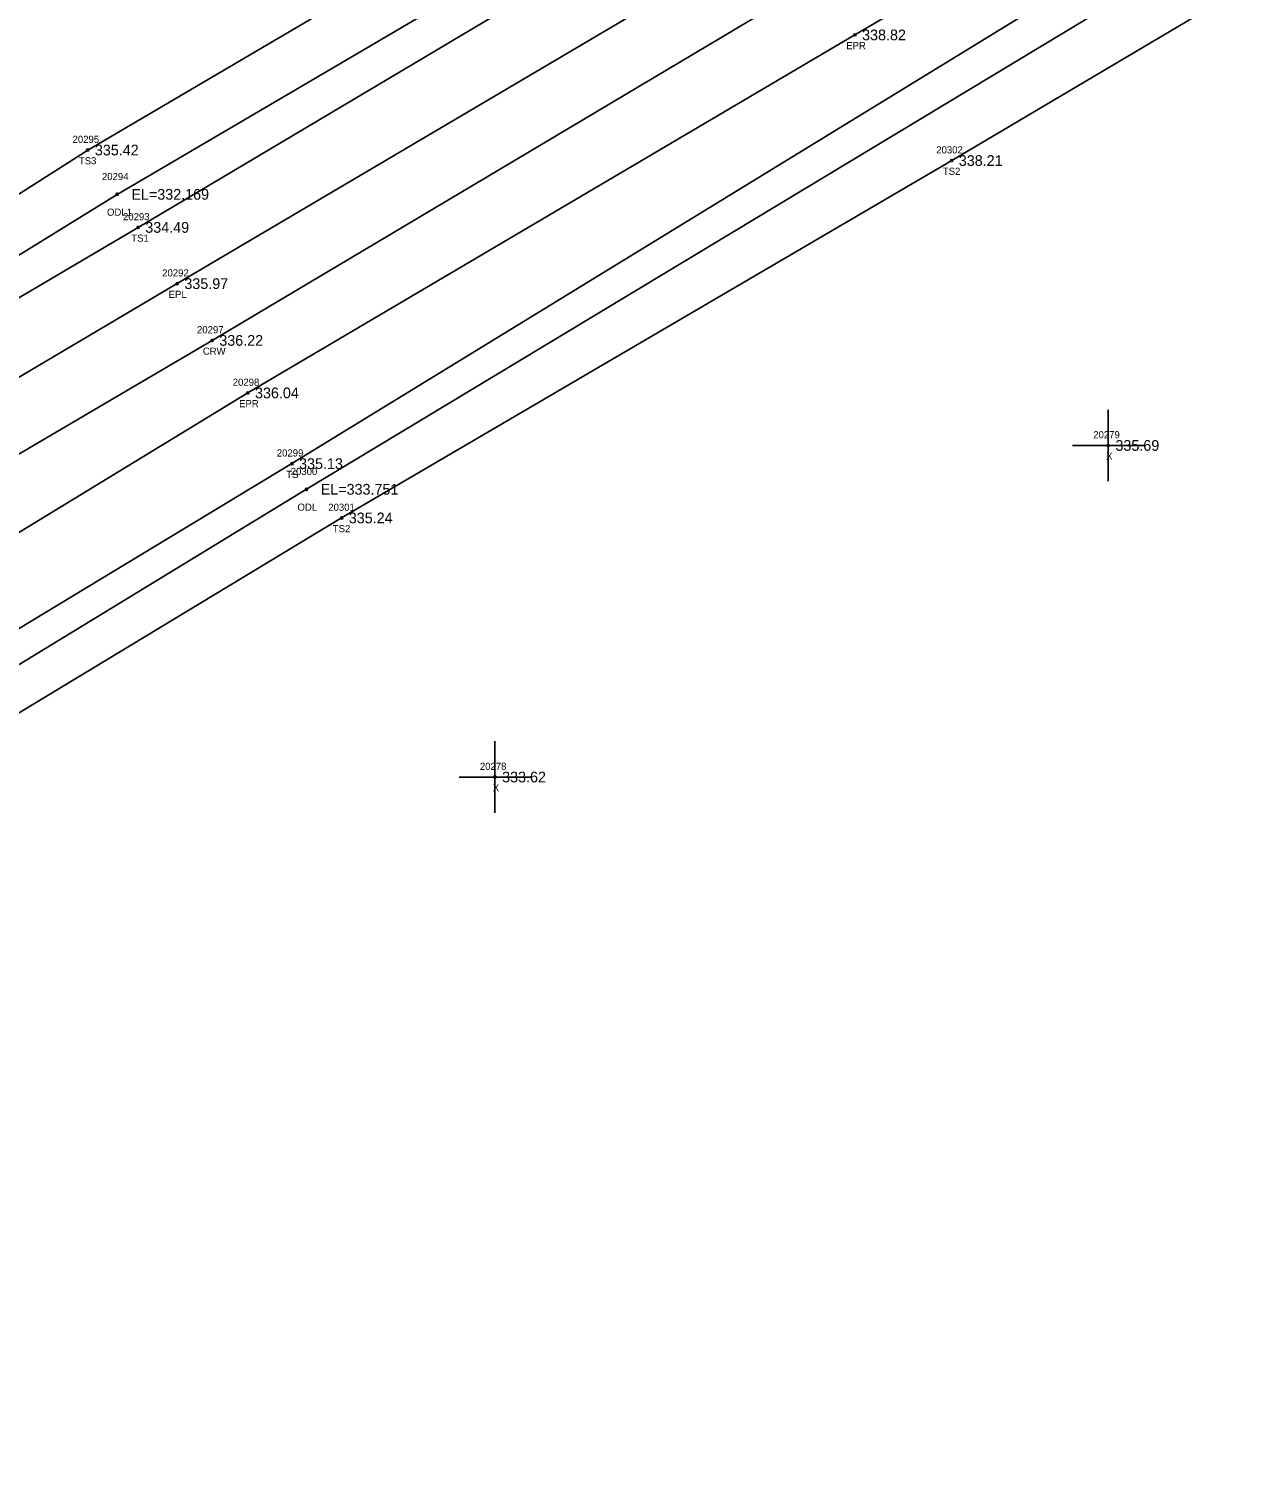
# Model space of a CAD drawing. Extents: x 2231109 to 2232328, y 1035718 to 1036919.
# Drawn here: x 2231830.7 to 2232002.6, y 1036455.4 to 1036655.6 of the extents above; entities that cross this region are included whole.
import ezdxf

# ---------------------------------------------------------------- set-up
doc = ezdxf.new("R2010")
doc.units = 0
for name, color, linetype in [('RD_DTM_BkLn1', 7, 'Continuous'), ('RD_DTM_BkLn2', 7, 'Continuous'), ('RD_DTM_BkLn_txCode', 7, 'Continuous'), ('RD_EX_H2O', 7, 'Continuous'), ('RD_EX_H2O_txCode', 7, 'Continuous'), ('RD_EX_Misc', 7, 'Continuous'), ('RD_EX_Misc_txCode', 7, 'Continuous'), ('RD_EX_Road', 7, 'Continuous'), ('RD_EX_Road_txCode', 7, 'Continuous'), ('RD_EX_TX_H2O_ELEV', 7, 'Continuous'), ('RD_EX_TX_Misc_ELEV', 7, 'Continuous'), ('RD_EX_TX_Road_ELEV', 7, 'Continuous'), ('RD_HC_Survey_ELEV', 7, 'Continuous'), ('RD_HC_Survey_txCode', 7, 'Continuous'), ('RD_SMD_Locator', 7, 'Continuous')]:
    doc.layers.add(name, color=color, linetype=linetype)

msp = doc.modelspace()

# ---------------------------------------------------------------- linework, layer by layer
at = {"layer": 'RD_DTM_BkLn1'}
msp.add_lwpolyline([(2231606.1, 1036462.92), (2231686.87, 1036511.89), (2231772.7, 1036562.84), (2231856.39, 1036612), (2231941.22, 1036662.52), (2232026.21, 1036712.41), (2232112.3, 1036762.07), (2232195.17, 1036811.63), (2232281.68, 1036862.71)], dxfattribs=at)
at = {"layer": 'RD_DTM_BkLn2'}
for points in [[(2231735.08, 1036566.99), (2231733.44, 1036571.38), (2231838.97, 1036638.65), (2231923.32, 1036688.26), (2232007.46, 1036737.64), (2232093.05, 1036790.84), (2232175.73, 1036838.16), (2232263.96, 1036889.44)], [(2231735.08, 1036566.99), (2231739.37, 1036565.02), (2231846.03, 1036627.82), (2231929.8, 1036677.63), (2232016.53, 1036728.58), (2232102.07, 1036778.24), (2232186.07, 1036826.97), (2232269.67, 1036876.59)], [(2231718.4, 1036498.96), (2231713.38, 1036506.48), (2231734.88, 1036516.5), (2231783.19, 1036543.78), (2231867.56, 1036594.75), (2232035.39, 1036697.6), (2232204.37, 1036795.95), (2232291.91, 1036847.83)], [(2231718.4, 1036498.96), (2231722.77, 1036493.83), (2231728.85, 1036494.16), (2231749.87, 1036507.43), (2231788.02, 1036534.9), (2231874.52, 1036587.15), (2231959.93, 1036637.18), (2232042.1, 1036685.84), (2232133.02, 1036735.49), (2232212.03, 1036786.36), (2232298.34, 1036837.91)]]:
    msp.add_lwpolyline(points, dxfattribs=at)
at = {"layer": 'RD_EX_H2O'}
for points in [[(2231741.7, 1036569.83), (2231843.08, 1036632.45), (2231926.34, 1036681.31), (2232011.09, 1036733.11), (2232099.56, 1036784.62), (2232183.31, 1036833.18), (2232266.22, 1036880.93)], [(2231720.77, 1036499.78), (2231736.43, 1036508.96), (2231742.17, 1036508.27), (2231745.29, 1036514.03), (2231785.52, 1036539.9), (2231869.59, 1036591.16), (2232038.46, 1036693), (2232129.43, 1036745.26), (2232207.65, 1036791.56), (2232294.95, 1036842.48)]]:
    msp.add_lwpolyline(points, dxfattribs=at)
at = {"layer": 'RD_EX_Misc'}
for p, q in [((2231981.86, 1036592.3), (2231981.86, 1036602.3)), ((2231976.86, 1036597.3), (2231986.86, 1036597.3)), ((2231895.99, 1036545.88), (2231895.99, 1036555.88)), ((2231890.99, 1036550.88), (2231900.99, 1036550.88))]:
    msp.add_line(p, q, dxfattribs=at)
at = {"layer": 'RD_EX_Road'}
for points in [[(2231606.1, 1036462.92), (2231601.27, 1036470.82), (2231681.58, 1036519.84), (2231764.99, 1036568.78), (2231851.5, 1036619.95), (2231935.62, 1036669.65), (2232021.78, 1036720.22), (2232106.75, 1036770.57), (2232190.54, 1036819.2), (2232275.92, 1036870.27)], [(2231606.1, 1036462.92), (2231610.57, 1036455.36), (2231692.09, 1036503.24), (2231706.07, 1036512.59), (2231777.1, 1036553.27), (2231861.39, 1036604.65), (2231946.39, 1036654.77), (2232031.07, 1036704.2), (2232117.06, 1036755.16), (2232199.91, 1036803.8), (2232286.7, 1036855.36)]]:
    msp.add_lwpolyline(points, dxfattribs=at)
at = {"layer": 'RD_SMD_Locator'}
for centre in [(2231946.39, 1036654.77), (2231838.97, 1036638.65), (2231959.93, 1036637.18), (2231843.08, 1036632.45), (2231846.03, 1036627.82), (2231851.5, 1036619.95), (2231856.39, 1036612), (2231861.39, 1036604.65), (2231981.86, 1036597.3), (2231867.56, 1036594.75), (2231869.59, 1036591.16), (2231874.52, 1036587.15), (2231895.99, 1036550.88)]:
    msp.add_circle(centre, 0.15, dxfattribs=at)

# ---------------------------------------------------------------- texts
at = {"layer": 'RD_DTM_BkLn_txCode'}
for s, p in [('20295', (2231836.85, 1036639.65)), ('20302', (2231957.77, 1036638.18)), ('TS3', (2231837.73, 1036636.65)), ('TS2', (2231958.69, 1036635.18)), ('20293', (2231843.91, 1036628.82)), ('TS1', (2231845.07, 1036625.82)), ('20299', (2231865.44, 1036595.75)), ('TS', (2231866.77, 1036592.75)), ('20301', (2231872.65, 1036588.15)), ('TS2', (2231873.28, 1036585.15))]:
    msp.add_text(s, height=1, dxfattribs=at).set_placement(p)
at = {"layer": 'RD_EX_H2O_txCode'}
for s, p in [('20294', (2231840.96, 1036634.45)), ('ODL1', (2231841.67, 1036629.45)), ('20300', (2231867.39, 1036593.16)), ('ODL', (2231868.34, 1036588.16))]:
    msp.add_text(s, height=1, dxfattribs=at).set_placement(p)
at = {"layer": 'RD_EX_Misc_txCode'}
for s, p in [('20279', (2231979.75, 1036598.3)), ('X', (2231981.55, 1036595.3)), ('20278', (2231893.87, 1036551.88)), ('X', (2231895.68, 1036548.88))]:
    msp.add_text(s, height=1, dxfattribs=at).set_placement(p)
at = {"layer": 'RD_EX_Road_txCode'}
for s, p in [('EPR', (2231945.16, 1036652.77)), ('20292', (2231849.39, 1036620.95)), ('EPL', (2231850.3, 1036617.95)), ('20298', (2231859.27, 1036605.65)), ('EPR', (2231860.16, 1036602.65))]:
    msp.add_text(s, height=1, dxfattribs=at).set_placement(p)
at = {"layer": 'RD_EX_TX_H2O_ELEV'}
for s, p in [('EL=332.169', (2231845.08, 1036631.7)), ('EL=333.751', (2231871.59, 1036590.41))]:
    msp.add_text(s, height=1.5, dxfattribs=at).set_placement(p)
at = {"layer": 'RD_EX_TX_Misc_ELEV'}
for s, p in [('335.42', (2231839.97, 1036637.9)), ('338.21', (2231960.93, 1036636.43)), ('334.49', (2231847.03, 1036627.07)), ('335.69', (2231982.86, 1036596.55)), ('335.13', (2231868.56, 1036594)), ('335.24', (2231875.52, 1036586.4)), ('333.62', (2231896.99, 1036550.13))]:
    msp.add_text(s, height=1.5, dxfattribs=at).set_placement(p)
at = {"layer": 'RD_EX_TX_Road_ELEV'}
for s, p in [('338.82', (2231947.39, 1036654.02)), ('335.97', (2231852.5, 1036619.2)), ('336.04', (2231862.39, 1036603.9))]:
    msp.add_text(s, height=1.5, dxfattribs=at).set_placement(p)
at = {"layer": 'RD_HC_Survey_ELEV'}
msp.add_text('336.22', height=1.5, dxfattribs=at).set_placement((2231857.39, 1036611.25))
at = {"layer": 'RD_HC_Survey_txCode'}
for s, p in [('20297', (2231854.27, 1036613)), ('CRW', (2231855.08, 1036610))]:
    msp.add_text(s, height=1, dxfattribs=at).set_placement(p)

doc.saveas('drawing.dxf')
